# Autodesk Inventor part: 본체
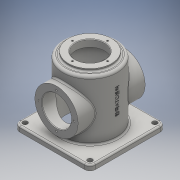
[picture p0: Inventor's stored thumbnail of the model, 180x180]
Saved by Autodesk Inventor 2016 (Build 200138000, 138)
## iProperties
Created: 2019-08
Part Number: 본체
Material: 일반
Document SubType Name: Modeling
Designer: user
Density: 1 g/cm^3
Appearance: 기본값
Mass: 414.921 g
Surface Area: 1160.05 cm^2
Volume: 414.921 cm^3
Author: user
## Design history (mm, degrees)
sketch "스케치1"
  geometry: L1 (-70, -70)-(70, -70); L2 (70, -70)-(70, 70); L3 (70, 70)-(-70, 70); L4 (-70, 70)-(-70, -70); L5 (-70, -70)-(70, 70); L6 (70, -70)-(-70, 70); 1 further point
  constraints: 12 end point, 2 midpoint, 2 parallel, 1 horizontal, 1 perpendicular
  dimensions: "d0" = 140 distance of L3.end L2.end; "d1" = 140 distance of L2.end L1.end
extrude "돌출1" new body sketch "스케치1" distance "d2" = 10; taper "d3" = 0 deg
sketch "스케치2"
  geometry: C1 r 50 at (0, 0); 1 further point
  constraints: 1 centre point, 1 coincident
  dimensions: "d4" = 100 diameter of C1
extrude "돌출2" join sketch "스케치2" distance "d5" = 110; taper "d6" = 0 deg
node "작업 평면1"
sketch "스케치3"
  geometry: C1 r 40 at (0, 0); 1 further point
  constraints: 1 centre point, 1 coincident
  dimensions: "d8" = 80 diameter of C1
extrude "돌출3" join sketch "스케치3" stored distance "d9" = 110; taper "d10" = 0 deg
sketch "스케치5" dims "d27" = 65
  geometry: 3 further points
  constraints: 2 horizontal alignment, 1 coincident, 2 other
hole "구멍3" sketch "스케치5" at (-32.5, 0) diameter "d28" = 3.242; stored, may be unused: countersink angle "d32" = 90 deg, drill point angle "d34" = 118 deg; dims "d29" = 8, "d30" = 4, "d31" = 2, "d33" = 10
node "작업 평면2"
sketch "스케치6"
  geometry: L1 (140, 0)-(0, 0) reference; L2 (0, 0)-(0, 10) reference; L3 (0, 10)-(140, 10) reference; L4 (140, 10)-(140, 0) reference; L5 (140, 0)-(0, 0) reference; L6 (0, 0)-(0, 10) reference; L7 (0, 10)-(140, 10) reference; L8 (140, 10)-(140, 0) reference; C1 r 40 at (70, 60); 1 further point
  constraints: 1 centre point
  dimensions: "d39" = 80 diameter of C1; "d40" = 60 distance from line of L1 C1.centre; "d41" = 70 distance from line of C1.centre L4
extrude "돌출4" join sketch "스케치6" distance "d42" = 124; taper "d43" = 0 deg
sketch "스케치7"
  geometry: 2 further points
  constraints: 1 coincident
hole "구멍4" sketch "스케치7" at (0, 0) diameter "d44" = 90; stored, may be unused: countersink angle "d48" = 90 deg, drill point angle "d50" = 0 deg; dims "d45" = 6, "d46" = 4, "d47" = 2, "d49" = 112
hole "구멍5" diameter "d53" = 54; stored, may be unused: countersink angle "d57" = 90 deg, drill point angle "d59" = 0 deg; dims "d51" = 10, "d52" = 10, "d54" = 6, "d55" = 4, "d56" = 2, "d58" = 13
hole "구멍6" diameter "d62" = 54; stored, may be unused: countersink angle "d66" = 90 deg, drill point angle "d68" = 0 deg; dims "d60" = 10, "d61" = 10, "d63" = 6, "d64" = 4, "d65" = 2, "d67" = 13
sketch "스케치8" dims "d69" = 65
  geometry: L1 (70, -60)-(-70, -60) reference; L2 (-70, -60)-(-70, -50) reference; L3 (-70, -50)-(70, -50) reference; L4 (70, -50)-(70, -60) reference; C1 r 27 at (0, 0) reference; C2 r 40 at (0, 0) reference; 3 further points
  constraints: 2 vertical alignment, 1 coincident, 2 other
hole "구멍7" sketch "스케치8" at (0, 32.5) diameter "d70" = 3.242; stored, may be unused: countersink angle "d74" = 90 deg, drill point angle "d76" = 118 deg; dims "d71" = 8, "d72" = 4, "d73" = 2, "d75" = 10
fillet "모깎기1" dims "d80" = 10
hole "구멍8" diameter "d83" = 9; stored, may be unused: countersink angle "d87" = 90 deg, drill point angle "d89" = 0 deg; dims "d81" = 10, "d82" = 10, "d84" = 8, "d85" = 4, "d86" = 2, "d88" = 10
hole "구멍9" diameter "d92" = 9; stored, may be unused: countersink angle "d96" = 90 deg, drill point angle "d98" = 0 deg; dims "d90" = 10, "d91" = 10, "d93" = 8, "d94" = 4, "d95" = 2, "d97" = 10
hole "구멍10" diameter "d101" = 9; stored, may be unused: countersink angle "d105" = 90 deg, drill point angle "d107" = 0 deg; dims "d99" = 10, "d100" = 10, "d102" = 8, "d103" = 4, "d104" = 2, "d106" = 10
hole "구멍11" diameter "d110" = 9; stored, may be unused: countersink angle "d114" = 90 deg, drill point angle "d116" = 0 deg; dims "d108" = 10, "d109" = 10, "d111" = 8, "d112" = 4, "d113" = 2, "d115" = 10
chamfer "모따기1" distance "d117" = 1; stored, may be unused: second distance "d118" = 2, angle "d119" = 45 deg
fillet "모깎기2" dims "d120" = 3
fillet "모깎기3" dims "d121" = 3
fillet "모깎기4" dims "d122" = 3
fillet "모깎기5" dims "d123" = 5
node "작업 평면3"
sketch "스케치9"
  geometry: 2 further points
  constraints: 1 horizontal alignment, 1 other
  dimensions: "d125" = 70 distance of point (0, 60) point (-70, 60)
feature "엠보싱1" sketch "스케치9" dims "d0" = 140, "d1" = 140, "d126" = 0.5, "d127" = 0
node "솔리드1"
pattern_circular "원형 패턴1" dims angle "d36" = 360 deg
pattern_circular "원형 패턴2" dims angle "d78" = 360 deg
mirror "대칭1"
node "절단 모서리 투영1"
node "절단 모서리 투영2"
node "절단 모서리 투영3"
other parameters: "d7" = -125, "d38" = -8, "d124" = 3.25
